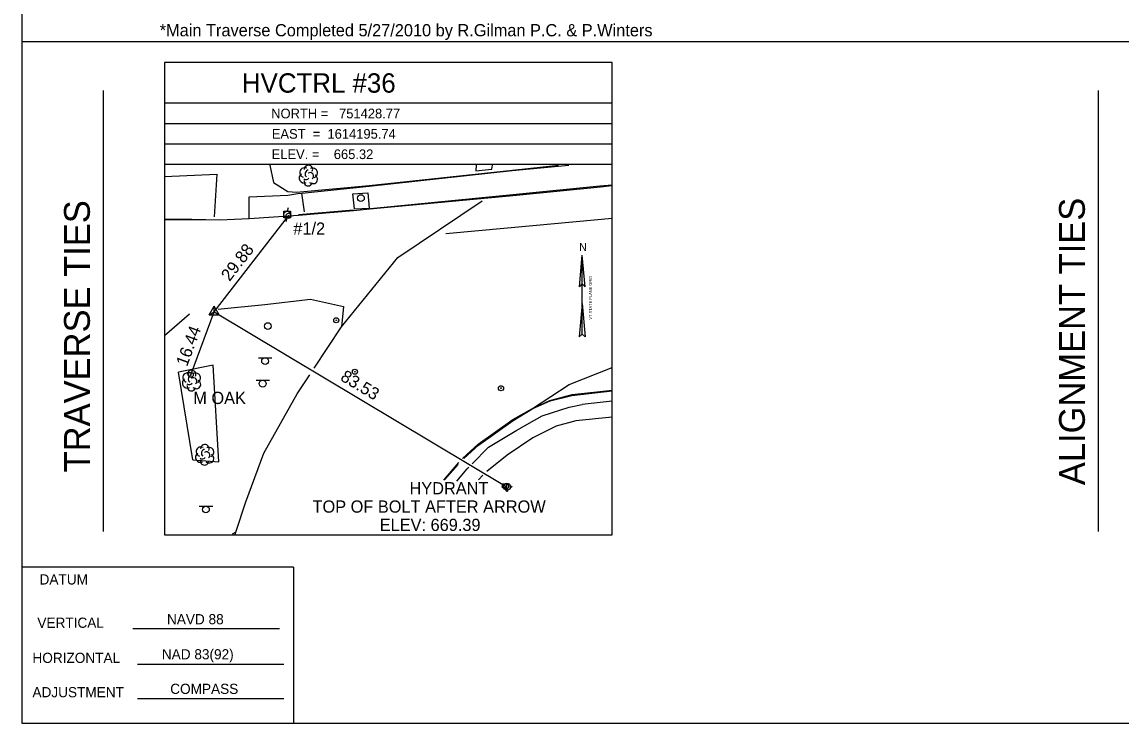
# Model space of a CAD drawing. Extents: x 1612431 to 1613071, y 750572 to 750992.
# Drawn here: x 1612431.1 to 1612701.1, y 750572.1 to 750744.3 of the extents above; entities that cross this region are included whole.
import ezdxf

# ---------------------------------------------------------------- set-up
doc = ezdxf.new("R2010")
doc.units = 0
for name, color, linetype in [('C_C', 7, 'Continuous'), ('CBP', 7, 'Continuous'), ('CPBM', 7, 'Continuous'), ('CPSM', 7, 'Continuous'), ('Default', 7, 'Continuous'), ('L_C', 7, 'Continuous'), ('LAPB', 7, 'Continuous'), ('LS', 7, 'Continuous'), ('LSH', 7, 'Continuous'), ('LTD', 7, 'Continuous'), ('LW', 7, 'Continuous'), ('NBL2', 7, 'Continuous'), ('NNA_P', 7, 'Continuous'), ('PET', 7, 'Continuous'), ('PSP', 7, 'Continuous'), ('RC', 7, 'Continuous'), ('RSW', 7, 'Continuous'), ('SSGN', 7, 'Continuous'), ('U_C', 7, 'Continuous'), ('UP', 7, 'Continuous'), ('UUMH', 7, 'Continuous'), ('UWFH', 7, 'Continuous'), ('UWV', 7, 'Continuous')]:
    doc.layers.add(name, color=color, linetype=linetype)

msp = doc.modelspace()

# ---------------------------------------------------------------- linework, layer by layer
at = {"layer": 'CBP'}
for centre, radius in [((1612496.64, 750696.67), 0.625), ((1612496.64, 750696.67), 0.0833), ((1612472.59, 750657.66), 0.625), ((1612472.59, 750657.66), 0.0833), ((1612550.05, 750630.23), 0.625), ((1612550.05, 750630.23), 0.0833)]:
    msp.add_circle(centre, radius, dxfattribs=at)
at = {"layer": 'CPBM'}
for p, q in [((1612549.16, 750629.9), (1612549.16, 750630.9)), ((1612549.16, 750630.9), (1612550.16, 750630.9)), ((1612550.16, 750629.9), (1612549.16, 750629.9)), ((1612549.67, 750630.4), (1612549.67, 750630.4)), ((1612549.67, 750630.4), (1612549.67, 750630.4)), ((1612550.16, 750630.9), (1612550.16, 750629.9))]:
    msp.add_line(p, q, dxfattribs=at)
at = {"layer": 'CPSM'}
for p, q in [((1612477.08, 750672.34), (1612478.33, 750674.5)), ((1612479.58, 750672.34), (1612478.33, 750674.5)), ((1612478.34, 750673.06), (1612478.33, 750674.5)), ((1612477.08, 750672.34), (1612478.34, 750673.06)), ((1612477.08, 750672.34), (1612479.58, 750672.34)), ((1612478.34, 750673.06), (1612478.34, 750673.06)), ((1612478.34, 750673.06), (1612479.58, 750672.34))]:
    msp.add_line(p, q, dxfattribs=at)
at = {"layer": 'Default'}
for p, q in [((1612478.33, 750673.06), (1612496.64, 750696.67)), ((1612472.59, 750657.66), (1612478.33, 750673.06)), ((1612478.33, 750673.06), (1612550.05, 750630.23))]:
    msp.add_line(p, q, dxfattribs=at)
at = {"layer": 'LAPB'}
for points in [[(1612473.09, 750636.72), (1612479.49, 750636.26), (1612478.13, 750660), (1612469.55, 750658.31)], [(1612473.09, 750636.72), (1612469.55, 750658.31)]]:
    msp.add_lwpolyline(points, dxfattribs=at)
at = {"layer": 'LS'}
for points in [[(1612512.8, 750698.39), (1612512.44, 750702.04), (1612516.11, 750702.32), (1612516.45, 750698.58)], [(1612512.8, 750698.39), (1612516.45, 750698.58)]]:
    msp.add_lwpolyline(points, dxfattribs=at)
at = {"layer": 'LSH'}
msp.add_line((1612501.45, 750706.61), (1612501.45, 750706.61), dxfattribs=at)
msp.add_line((1612501.45, 750706.61), (1612501.45, 750706.61), dxfattribs=at)
for start, end in [(96.469, 180.9563), (335.5272, 83.531)]:
    msp.add_arc((1612501.5, 750708.05), 1.05, start, end, dxfattribs=at)
for centre, major_axis, ratio, start_param, end_param in [((1612500.37, 750705.9), (0.58, -1.04), 0.959034, 3.141593, 6.283185), ((1612500.66, 750707.28), (1.21, -0.51), 0.895232, 1.570796, 4.712389), ((1612501.24, 750707.07), (-0.208, -0.792), 0.645439, 3.141593, 6.283185), ((1612501.95, 750706.45), (-0.5, 0.667), 0.989748, 3.141593, 6.283185), ((1612502.49, 750707.2), (-1.14, -0.48), 0.949671, 1.570796, 4.712389), ((1612501.45, 750705.11), (0.26, 1.06), 0.942809, 1.570796, 4.712389), ((1612500.99, 750705.86), (-0.625, -0.083), 0.423636, 0, 3.141593), ((1612502.45, 750705.78), (-1.09, 0.79), 0.841452, 1.570796, 4.712389)]:
    msp.add_ellipse(centre, major_axis=major_axis, ratio=ratio, start_param=start_param, end_param=end_param, dxfattribs=at)
at = {"layer": 'LTD'}
for p, q in [((1612472.75, 750656.27), (1612472.75, 750656.27)), ((1612472.75, 750656.27), (1612472.75, 750656.27)), ((1612475.99, 750638.05), (1612475.99, 750638.05)), ((1612475.99, 750638.05), (1612475.99, 750638.05))]:
    msp.add_line(p, q, dxfattribs=at)
for centre in [(1612472.8, 750657.7), (1612476.04, 750639.48)]:
    msp.add_arc(centre, 1.05, 335.5272, 180.9563, dxfattribs=at)
for centre, major_axis, ratio, start_param, end_param in [((1612471.96, 750656.93), (1.21, -0.51), 0.895232, 1.570796, 4.712389), ((1612471.67, 750655.56), (0.58, -1.04), 0.959034, 3.141593, 6.283185), ((1612472.29, 750655.52), (-0.625, -0.083), 0.423636, 0, 3.141593), ((1612472.54, 750656.73), (-0.208, -0.792), 0.645439, 3.141593, 6.283185), ((1612473.25, 750656.1), (-0.5, 0.667), 0.989748, 3.141593, 6.283185), ((1612473.75, 750655.43), (-1.09, 0.79), 0.841452, 1.570796, 4.712389), ((1612473.79, 750656.85), (-1.14, -0.48), 0.949671, 1.570796, 4.712389), ((1612472.75, 750654.77), (0.26, 1.06), 0.942809, 1.570796, 4.712389), ((1612475.2, 750638.71), (1.21, -0.51), 0.895232, 1.570796, 4.712389), ((1612477.03, 750638.63), (-1.14, -0.48), 0.949671, 1.570796, 4.712389), ((1612474.91, 750637.34), (0.58, -1.04), 0.959034, 3.141593, 6.283185), ((1612475.99, 750636.55), (0.26, 1.06), 0.942809, 1.570796, 4.712389), ((1612475.53, 750637.3), (-0.625, -0.083), 0.423636, 0, 3.141593), ((1612475.78, 750638.5), (-0.208, -0.792), 0.645439, 3.141593, 6.283185), ((1612476.49, 750637.88), (-0.5, 0.667), 0.989748, 3.141593, 6.283185), ((1612476.99, 750637.21), (-1.09, 0.79), 0.841452, 1.570796, 4.712389)]:
    msp.add_ellipse(centre, major_axis=major_axis, ratio=ratio, start_param=start_param, end_param=end_param, dxfattribs=at)
at = {"layer": 'LW'}
msp.add_lwpolyline([(1612491.99, 750709.09), (1612492.89, 750704.86), (1612496.48, 750702.67), (1612498.58, 750702.46)], dxfattribs=at)
at = {"layer": 'NBL2'}
for p, q in [((1612431.13, 750739.46), (1613071.13, 750739.46)), ((1612451.13, 750619.13), (1612451.13, 750727.46)), ((1612695.58, 750619.13), (1612695.58, 750727.46)), ((1612576.13, 750724.3), (1612466.13, 750724.3)), ((1612576.13, 750719.3), (1612466.13, 750719.3)), ((1612576.13, 750714.3), (1612466.13, 750714.3)), ((1612576.13, 750709.3), (1612466.13, 750709.3)), ((1612497.8, 750610.38), (1612431.13, 750610.38)), ((1612497.8, 750610.38), (1612497.8, 750572.13)), ((1612497.8, 750610.38), (1612497.8, 750572.13)), ((1612458.37, 750595.36), (1612494.37, 750595.33)), ((1612459.48, 750586.58), (1612495.48, 750586.58)), ((1612459.48, 750578.15), (1612495.48, 750578.12))]:
    msp.add_line(p, q, dxfattribs=at)
for points in [[(1612431.13, 750572.13), (1613071.13, 750572.13), (1613071.13, 750992.13), (1612431.13, 750992.13)], [(1612466.13, 750618.3), (1612576.13, 750618.3), (1612576.13, 750734.3), (1612466.13, 750734.3)]]:
    msp.add_lwpolyline(points, close=True, dxfattribs=at)
at = {"layer": 'NNA_P'}
for p, q in [((1612568.08, 750679.21), (1612568.77, 750687)), ((1612568.78, 750667.63), (1612568.77, 750687)), ((1612569.47, 750679.21), (1612568.77, 750687)), ((1612568.08, 750679.21), (1612568.77, 750679.97)), ((1612569.47, 750679.21), (1612568.77, 750679.97)), ((1612568.78, 750675.15), (1612568.05, 750666.99)), ((1612568.77, 750675.15), (1612569.5, 750666.99)), ((1612568.78, 750667.63), (1612568.05, 750666.99)), ((1612568.78, 750667.63), (1612569.5, 750666.99))]:
    msp.add_line(p, q, dxfattribs=at)
at = {"layer": 'PET'}
for points in [[(1612466.13, 750695.79), (1612479.72, 750695.73), (1612486.92, 750696), (1612499.06, 750696.82), (1612512.54, 750697.98), (1612516.59, 750698.42), (1612552.61, 750701.74)], [(1612502.9, 750659.23), (1612509.64, 750669.45), (1612523.47, 750686.46), (1612544.16, 750700.32)], [(1612535.28, 750692.32), (1612557.51, 750694.38), (1612576.13, 750696.1)], [(1612479.35, 750673.75), (1612480.05, 750673.87), (1612490.82, 750674.92), (1612501.99, 750676.22), (1612510.1, 750674.38), (1612509.64, 750669.45)], [(1612466.13, 750667.26), (1612472.29, 750672.58)], [(1612539.34, 750637.05), (1612543.23, 750640.62), (1612551.73, 750646.63), (1612556.51, 750649.4), (1612565.55, 750655.22), (1612576.13, 750659.46)], [(1612483.51, 750618.49), (1612483.67, 750618.96), (1612486.15, 750626.42), (1612490.53, 750638.38), (1612498.76, 750652.96), (1612501.84, 750657.63)], [(1612534.77, 750631.73), (1612538.45, 750636.08)], [(1612483.67, 750618.96), (1612482.75, 750618.49)]]:
    msp.add_lwpolyline(points, dxfattribs=at)
at = {"layer": 'PSP'}
for points in [[(1612552.61, 750701.74), (1612573.23, 750703.82), (1612576.13, 750704.13)], [(1612556.51, 750649.4), (1612560.79, 750651.32), (1612566.28, 750652.77), (1612576.13, 750653.85)]]:
    msp.add_lwpolyline(points, dxfattribs=at)
at = {"layer": 'RC'}
for points in [[(1612498.58, 750702.46), (1612516.46, 750704.08), (1612551.6, 750707.89), (1612562.97, 750709.09)], [(1612516.71, 750698.5), (1612552.5, 750701.96), (1612573.09, 750704.02)], [(1612499.08, 750696.99), (1612512.56, 750698.15)], [(1612466.13, 750695.94), (1612472.82, 750695.84), (1612479.72, 750695.73)], [(1612539.68, 750637.12), (1612543.3, 750640.39), (1612551.78, 750646.41), (1612556.65, 750649.34), (1612560.85, 750651.21), (1612566.21, 750652.54), (1612576.13, 750653.66)], [(1612534.99, 750631.92), (1612538.25, 750635.64)]]:
    msp.add_lwpolyline(points, dxfattribs=at)
at = {"layer": 'RSW'}
for points in [[(1612466.13, 750706.3), (1612478.97, 750706.94), (1612478.35, 750696.42)], [(1612500.56, 750697.67), (1612499.88, 750702.27), (1612516.41, 750703.97), (1612551.57, 750707.81), (1612565.45, 750709.09)], [(1612542.68, 750709.09), (1612542.6, 750707.74), (1612546.56, 750708.13), (1612546.74, 750709.09)], [(1612573.09, 750704.02), (1612576.13, 750704.28)], [(1612486.92, 750696), (1612486.96, 750701.37), (1612496.46, 750701.77), (1612498.91, 750702.13), (1612499.88, 750702.27)], [(1612541.72, 750635.78), (1612545.71, 750639.87), (1612552.67, 750644.08), (1612558.9, 750647.52), (1612565.57, 750649.67), (1612568.73, 750650.36)], [(1612576.13, 750651.18), (1612568.73, 750650.36)], [(1612576.13, 750647.27), (1612567.21, 750646.33), (1612562.35, 750645.02), (1612556.63, 750642.14), (1612550.29, 750637.92), (1612545.36, 750633.91)], [(1612537.95, 750631.5), (1612540.51, 750634.54), (1612540.89, 750634.92)], [(1612544.33, 750632.96), (1612543.29, 750631.85)]]:
    msp.add_lwpolyline(points, dxfattribs=at)
at = {"layer": 'SSGN'}
for p, q in [((1612489.21, 750661.84), (1612492.55, 750661.84)), ((1612490.86, 750661.01), (1612490.86, 750661.01)), ((1612488.62, 750656.29), (1612491.96, 750656.29)), ((1612490.27, 750655.46), (1612490.27, 750655.46)), ((1612474.66, 750625.39), (1612478, 750625.39)), ((1612476.31, 750624.56), (1612476.31, 750624.56))]:
    msp.add_line(p, q, dxfattribs=at)
for centre in [(1612490.86, 750661.01), (1612490.27, 750655.46), (1612476.31, 750624.56)]:
    msp.add_circle(centre, 0.833, dxfattribs=at)
at = {"layer": 'UP'}
for p, q in [((1612495.44, 750696.14), (1612495.44, 750697.81)), ((1612495.44, 750697.81), (1612497.1, 750697.81)), ((1612497.1, 750696.14), (1612495.44, 750696.14)), ((1612496.02, 750695.31), (1612496.27, 750696.14)), ((1612496.52, 750698.64), (1612496.27, 750697.81)), ((1612496.27, 750696.98), (1612496.27, 750696.98)), ((1612497.1, 750697.81), (1612497.1, 750696.14))]:
    msp.add_line(p, q, dxfattribs=at)
msp.add_circle((1612496.27, 750696.98), 0.833, dxfattribs=at)
at = {"layer": 'UUMH'}
for p, q in [((1612514.39, 750701.02), (1612514.39, 750701.02)), ((1612515.23, 750701.02), (1612515.23, 750701.02)), ((1612491.52, 750669.6), (1612491.52, 750669.6)), ((1612492.35, 750669.6), (1612492.35, 750669.6))]:
    msp.add_line(p, q, dxfattribs=at)
for centre in [(1612514.39, 750701.02), (1612491.52, 750669.6)]:
    msp.add_circle(centre, 0.833, dxfattribs=at)
at = {"layer": 'UWFH'}
msp.add_line((1612550.27, 750630.16), (1612550.27, 750630.16), dxfattribs=at)
for centre, radius in [((1612549.27, 750630.16), 0.167), ((1612550.27, 750630.16), 0.833), ((1612550.27, 750629.16), 0.167), ((1612551.27, 750630.16), 0.167)]:
    msp.add_circle(centre, radius, dxfattribs=at)
at = {"layer": 'UWV'}
for centre, radius in [((1612508.34, 750671.02), 0.625), ((1612508.34, 750671.02), 0.0833), ((1612512.93, 750658.39), 0.625), ((1612512.93, 750658.39), 0.0833), ((1612548.81, 750654.34), 0.625), ((1612548.81, 750654.34), 0.0833)]:
    msp.add_circle(centre, radius, dxfattribs=at)

# ---------------------------------------------------------------- texts
at = {"layer": 'C_C'}
for s, p in [('HYDRANT', (1612526.33, 750628.28)), ('TOP OF BOLT AFTER ARROW', (1612502.51, 750623.78)), ('ELEV: 669.39', (1612519.02, 750619.28))]:
    msp.add_text(s, height=3, dxfattribs=at).set_placement(p)
at = {"layer": 'Default'}
msp.add_text('*Main Traverse Completed 5/27/2010 by R.Gilman P.C. & P.Winters', height=3, dxfattribs=at).set_placement((1612464.97, 750740.75))
for s, rotation, p in [('29.88', 52.2128, (1612482.14, 750680.42)), ('16.44', 69.5375, (1612471.68, 750659.52)), ('83.53', 329.1562, (1612509.13, 750656.42))]:
    msp.add_text(s, height=3, rotation=rotation, dxfattribs=at).set_placement(p)
at = {"layer": 'L_C'}
msp.add_text('M OAK', height=3, dxfattribs=at).set_placement((1612473.21, 750650.46))
at = {"layer": 'NBL2'}
for s, height, p in [('     HVCTRL #36    ', 4.75, (1612476.34, 750726.92)), ('NORTH =   751428.77 ', 2.375, (1612492.35, 750720.61)), ('EAST  =  1614195.74 ', 2.375, (1612492.5, 750715.61)), ('ELEV. =    665.32   ', 2.375, (1612492.46, 750710.61)), ('DATUM', 2.5, (1612435.45, 750606.14)), ('  NAVD 88 ', 2.5, (1612464.89, 750596.37)), ('HORIZONTAL', 2.5, (1612433.7, 750586.88)), ('NAD 83(92) ', 2.5, (1612465.49, 750587.76)), ('ADJUSTMENT', 2.5, (1612433.7, 750578.45)), ('  COMPASS ', 2.5, (1612465.69, 750579.27))]:
    msp.add_text(s, height=height, dxfattribs=at).set_placement(p)
for s, height, rotation, p in [('TRAVERSE TIES', 6.3332, 90, (1612447.8, 750633.68)), ('ALIGNMENT TIES', 6.3332, 90, (1612692.24, 750630.53)), ('VERTICAL', 2.5, 0.1439, (1612434.91, 750595.48))]:
    msp.add_text(s, height=height, rotation=rotation, dxfattribs=at).set_placement(p)
at = {"layer": 'NNA_P'}
msp.add_text('N', height=1.97, dxfattribs=at).set_placement((1612568.01, 750688.01))
msp.add_text('VT STATE PLANE GRID', height=0.7, rotation=90.0204, dxfattribs=at).set_placement((1612571.13, 750671.19))
at = {"layer": 'U_C'}
msp.add_text('#1/2', height=3, dxfattribs=at).set_placement((1612497.79, 750692.05))

doc.saveas('drawing.dxf')
